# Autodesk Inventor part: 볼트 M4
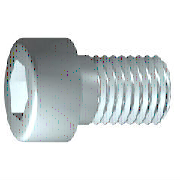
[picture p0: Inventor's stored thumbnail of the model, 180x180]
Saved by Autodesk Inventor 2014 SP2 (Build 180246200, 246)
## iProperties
IsCustomPart: 0
Created: 2014-10
Part Number: 볼트 M4
Material: 강철, 연강
Description: 6각머리 태핑 나사
Document SubType Name: Modeling
Standard: KS B 1003
Designer: KYOUNG IL JANG
Standards Organization: KS
Language: ko-KR
Size Designation: M 4 x 10
Categories: <MemberInstance><Categories><Category DisplayName="조임쇠" InternalName="e4da775c-781d-43d5-af7c-5136215cf5a6" Mnemonic="FSTN"><Category DisplayName="볼트" InternalN
Density: 7.86 g/cm^3
Mass: 2.0371 g
Surface Area: 3.0572 cm^2
Volume: 0.259174 cm^3
Appearance: 강철 - 광택
Author: SeoGD™ [www.esajin.kr]
Revision Number: 1
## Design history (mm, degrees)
sketch "스케치1"
  geometry: L1 (-1, 0)-(10, 0); L2 (10, 0)-(10, 2); L3 (10, 2)-(1.75, 2); L4 (1.75, 2)-(1.32, 2); L5 (1.32, 2)-(0, 2); L6 (0, 2)-(0, 3.5); L7 (0, 3.5)-(-4, 3.5); L8 (-4, 3.5)-(-4, 1.732); L9 (-4, 1.732)-(-2, 1.732); L10 (-2, 1.732)-(-1, 0); L11 (-6.8, 0)-(12.8, 0) reference; L12 (0, -0.7)-(0, 4.2) reference; L13 (1.75, 2)-(0, 2)
  constraints: 22 end point, 6 parallel, 2 collinear, 2 perpendicular, 1 horizontal, 1 point on line
  dimensions: "d1" = 8.25 distance from line of L3.end L2 (= GEL); "d2" = 0.42952 distance of L4.end L3.end (computed from GAL); "d3" = 4 distance between parallel lines of L8 L6 (= KOH); "d4" = 2 distance of L8.end L9.end (= INTI); "d5" = 60 deg angle of L10 L1; "d6" = 4 diameter of L3 L1 (= GD); "d7" = 4 diameter of L5 L1 (= BDM); "d8" = 3.4641 diameter of L9 L1 (= 1.1547 x SW); "d9" = 7 diameter of L7 L1 (= KOD); "d26" = 10 distance between parallel lines of L12 L2 (= NLG)
revolve "본체" sketch "스케치1" stored, may be unused: angle "d10" = 90 deg
sketch "스케치2"
  geometry: L1 (0, -4.9)-(0, 4.9) reference; L2 (-4.9, 0)-(4.9, 0) reference; L3 (1.732, 0)-(0.866, -1.5); L4 (0.866, -1.5)-(-0.866, -1.5); L5 (-0.866, -1.5)-(-1.732, 0); L6 (-1.732, 0)-(-0.866, 1.5); L7 (-0.866, 1.5)-(0.866, 1.5); L8 (0.866, 1.5)-(1.732, 0); 2 further points
  constraints: 12 end point, 1 coincident, 1 horizontal alignment, 1 point on line, 12 other
extrude "슬롯" join sketch "스케치2" stored distance "d11" = 10; taper "d12" = 0 deg
workplane "Work Plane1"
fillet "Fillet2" dims "d30" = 0.1 (= R)
body "Solid1"
fillet "모깎기1" dims "d17" = 0.4 (= RR)
feature "스레드" dims "d13" = 8.25 (= GEL), "d14" = 0
chamfer "모따기1" distance "d15" = 0.42941 (= -0.5 x SPD + 0.5 x GD); stored, may be unused: second distance "d16" = 0.42941 (= GUL), angle "d27" = 45 deg
other parameters: "GD" = 4 (= NND) [user parameter; used in 2 equation terms], "NLG" = 10 [user parameter; used in 1 equation term], "GEL" = 8.25 [user parameter; used in 2 equation terms], "KOD" = 7 [user parameter; used in 1 equation term], "KOH" = 4 [user parameter; used in 1 equation term], "INTI" = 2 [user parameter; used in 1 equation term], "GAL" = 0.42941 (= 0.61345 x PTC) [user parameter; used in 1 equation term], "GUL" = 0.42941 (= 0.61345 x PTC) [user parameter; used in 1 equation term], "BDM" = 4 (= NND) [user parameter; used in 1 equation term], "SW" = 3 [user parameter; used in 2 equation terms], "RR" = 0.4 [user parameter; used in 1 equation term], "SPD" = 3.14117 (= NND - 1.2269 x PTC) [user parameter; used in 1 equation term], "d19" = 0, "d28" = 0, "d29" = 0, "R" = 0.1 [user parameter; used in 1 equation term], "PHH" = 0.2 [user parameter], "GD1" = 3.14117 (= THREADDIA - 1.2269 x PTC) [user parameter], "THREADDIA" = 4 [user parameter; used in 1 equation term], "FAWI" = 45 deg [user parameter], "TPU" = 14.28571 (computed from PTC) [user parameter], "PTC" = 0.7 [user parameter; used in 5 equation terms], "NND" = 4 [user parameter; used in 3 equation terms], "TOA" = 30 deg [user parameter], "E0" = 3.465 (= 1.155 x SW) [user parameter]
